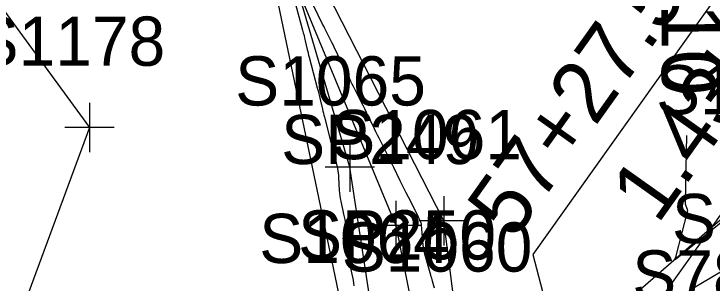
# Model space of a CAD drawing. Extents: x 816928 to 825690, y 436959 to 448212.
# Drawn here: x 818922.8 to 818979.4, y 445230.1 to 445252 of the extents above; entities that cross this region are included whole.
import ezdxf

# ---------------------------------------------------------------- set-up
doc = ezdxf.new("R2010")
doc.units = 0
for name, color, linetype in [('SURVEY - CONTOURS - Index with Text', 7, 'Continuous'), ('SURVEY - CONTOURS - Intermediate with optional Text', 7, 'Continuous'), ('SURVEY - DRAINAGE - Bridges Text', 7, 'Continuous'), ('SURVEY - DTM - Breaklines', 7, 'Continuous'), ('SURVEY - DTM - Breaklines - Points - Locators', 7, 'Continuous'), ('SURVEY - DTM - Breaklines - Points - Numbers', 7, 'Continuous'), ('SURVEY - PROPERTY - Parcels', 7, 'Continuous'), ('SURVEY - PROPERTY - ROW Lines', 7, 'Continuous'), ('SURVEY - UTILITIES - Telephone (Underground) - Points - Numbers', 7, 'Continuous'), ('SURVEY - VEGETATION - Features - Points - Locators', 7, 'Continuous'), ('SURVEY - VEGETATION - Features - Points - Numbers', 7, 'Continuous'), ('SURVEY - VEGETATION - Features with Text', 7, 'Continuous')]:
    doc.layers.add(name, color=color, linetype=linetype)

msp = doc.modelspace()

# ---------------------------------------------------------------- linework, layer by layer
at = {"layer": 'SURVEY - CONTOURS - Index with Text'}
msp.add_lwpolyline([(818977.365, 445242.093), (818977.255, 445236.694), (818977.257, 445236.612), (818977.268, 445236.531), (818977.287, 445236.452), (818977.314, 445236.374), (818977.416, 445236.122), (818977.433, 445236.067), (818977.441, 445236.012), (818977.44, 445235.957), (818977.43, 445235.901), (818976.493, 445232.325), (818976.491, 445232.318), (818976.491, 445232.312), (818976.492, 445232.305), (818976.494, 445232.299), (818976.503, 445232.277), (818976.505, 445232.273), (818976.505, 445232.268), (818976.505, 445232.264), (818976.504, 445232.259), (818976.433, 445232.064), (818976.424, 445232.031), (818976.427, 445232.016), (818976.443, 445232.018), (818976.471, 445232.037), (818976.698, 445232.223), (818976.7, 445232.225), (818976.702, 445232.226), (818976.704, 445232.227), (818976.706, 445232.229), (818976.712, 445232.232), (818976.713, 445232.233), (818976.715, 445232.234), (818976.716, 445232.235), (818976.717, 445232.236), (818980.448, 445235.262)], dxfattribs=at)
at = {"layer": 'SURVEY - CONTOURS - Intermediate with optional Text'}
for points in [[(818945.447, 445253.599), (818946.234, 445250.644), (818946.29, 445250.429), (818946.345, 445250.213), (818946.398, 445249.996), (818946.448, 445249.779), (818946.611, 445249.07), (818946.646, 445248.918), (818946.683, 445248.767), (818946.721, 445248.615), (818946.76, 445248.464), (818947.423, 445245.954), (818947.484, 445245.719), (818947.543, 445245.483), (818947.601, 445245.247), (818947.656, 445245.01), (818947.835, 445244.236), (818947.874, 445244.07), (818947.914, 445243.905), (818947.955, 445243.74), (818947.998, 445243.575), (818948.611, 445241.234), (818948.676, 445240.983), (818948.739, 445240.731), (818948.801, 445240.478), (818948.86, 445240.226), (818949.052, 445239.399), (818949.089, 445239.221), (818949.118, 445239.042), (818949.139, 445238.862), (818949.152, 445238.681), (818949.202, 445237.637), (818949.217, 445237.414), (818949.243, 445237.192), (818949.278, 445236.971), (818949.323, 445236.752), (818949.559, 445235.715), (818949.606, 445235.492), (818949.644, 445235.268), (818949.673, 445235.042), (818949.694, 445234.815), (818949.823, 445233.081), (818949.855, 445232.734), (818949.899, 445232.389), (818949.957, 445232.046), (818950.026, 445231.705), (818950.274, 445230.593), (818950.324, 445230.354), (818950.365, 445230.114), (818950.399, 445229.873)], [(818956.932, 445229.705), (818956.771, 445230.266), (818956.736, 445230.386), (818956.702, 445230.506), (818956.667, 445230.626), (818956.633, 445230.746), (818956.197, 445232.263), (818956.117, 445232.57), (818956.054, 445232.879), (818956.007, 445233.191), (818955.975, 445233.506), (818955.876, 445234.845), (818955.868, 445234.913), (818955.854, 445234.979), (818955.833, 445235.044), (818955.805, 445235.107), (818955.706, 445235.31), (818955.684, 445235.353), (818955.663, 445235.397), (818955.641, 445235.44), (818955.619, 445235.483), (818954.809, 445237.095), (818954.644, 445237.424), (818954.48, 445237.753), (818954.317, 445238.083), (818954.155, 445238.413), (818953.626, 445239.491), (818953.513, 445239.722), (818953.399, 445239.953), (818953.284, 445240.183), (818953.169, 445240.413), (818952.566, 445241.611), (818952.437, 445241.868), (818952.309, 445242.125), (818952.182, 445242.383), (818952.056, 445242.641), (818951.409, 445243.964), (818951.27, 445244.248), (818951.13, 445244.531), (818950.99, 445244.813), (818950.848, 445245.096), (818950.363, 445246.06), (818950.259, 445246.267), (818950.156, 445246.475), (818950.054, 445246.682), (818949.952, 445246.89), (818949.1, 445248.641), (818948.978, 445248.89), (818948.855, 445249.139), (818948.732, 445249.387), (818948.608, 445249.635), (818948.2, 445250.444), (818948.113, 445250.618), (818948.027, 445250.792), (818947.941, 445250.966), (818947.857, 445251.14), (818946.757, 445253.409)], [(818980.118, 445230.994), (818977.936, 445229.697)]]:
    msp.add_lwpolyline(points, dxfattribs=at)
at = {"layer": 'SURVEY - DRAINAGE - Bridges Text'}
msp.add_line((818986.837, 445263.289), (818964.904, 445232.428), dxfattribs=at)
msp.add_lwpolyline([(818964.904, 445232.428), (818977.092, 445185.746)], dxfattribs=at)
at = {"layer": 'SURVEY - DTM - Breaklines'}
for points in [[(819073.298, 445355.122), (819048.115, 445322.006), (819023.42, 445284.723), (818992.563, 445243.615), (818984.238, 445238.804), (818960.537, 445218.165), (818958.862, 445226.04), (818957.684, 445235.166), (818941.199, 445267.453), (818950.993, 445220.447), (818950.259, 445210.542), (818939.42, 445207.694)], [(818955.127, 445214.291), (818952.003, 445226.736), (818950.052, 445239.527), (818945.78, 445254.112), (818953.794, 445234.774), (818955.325, 445227.021), (818958.675, 445215.535)]]:
    msp.add_lwpolyline(points, dxfattribs=at)
at = {"layer": 'SURVEY - DTM - Breaklines - Points - Locators'}
for p, q in [((818950.052, 445241.527), (818950.052, 445237.527)), ((818952.052, 445239.527), (818948.052, 445239.527)), ((818957.684, 445237.166), (818957.684, 445233.166)), ((818953.794, 445236.774), (818953.794, 445232.774)), ((818959.684, 445235.166), (818955.684, 445235.166)), ((818955.794, 445234.774), (818951.794, 445234.774))]:
    msp.add_line(p, q, dxfattribs=at)
at = {"layer": 'SURVEY - PROPERTY - Parcels'}
msp.add_line((818939.168, 445178.006), (819170.276, 445503.188), dxfattribs=at)
at = {"layer": 'SURVEY - PROPERTY - ROW Lines'}
msp.add_line((818939.168, 445178.006), (819182.874, 445520.914), dxfattribs=at)
at = {"layer": 'SURVEY - VEGETATION - Features - Points - Locators'}
for p, q in [((818928.958, 445244.751), (818928.958, 445240.751)), ((818930.958, 445242.751), (818926.958, 445242.751))]:
    msp.add_line(p, q, dxfattribs=at)
at = {"layer": 'SURVEY - VEGETATION - Features with Text'}
msp.add_lwpolyline([(818921.649, 445531.075), (818911.357, 445419.447), (818895.02, 445347.602), (818900.539, 445320.739), (818919.801, 445285.725), (818871.556, 445256.506), (818910.143, 445268.505), (818928.958, 445242.751), (818875.35, 445097.529)], dxfattribs=at)

# ---------------------------------------------------------------- texts
at = {"layer": 'SURVEY - CONTOURS - Index with Text'}
msp.add_text('310', height=5, rotation=270.52, dxfattribs=at).set_placement((818975.292, 445256.499))
at = {"layer": 'SURVEY - DRAINAGE - Bridges Text'}
for s, p in [('57+27.53', (818963.376, 445233.515)), ("1.43'", (818975.022, 445234.798))]:
    msp.add_text(s, height=5, rotation=54.5985, dxfattribs=at).set_placement(p)
at = {"layer": 'SURVEY - DTM - Breaklines - Points - Numbers'}
for s, p in [('S1065', (818940.764, 445244.527)), ('S1058', (818974.903, 445243.804)), ('S1061', (818948.554, 445240.166)), ('SP249', (818944.49, 445239.774)), ('S1029', (818976.188, 445233.351)), ('S1064', (818942.715, 445231.736)), ('SP250', (818945.864, 445232.021)), ('S1060', (818949.401, 445231.04))]:
    msp.add_text(s, height=4, dxfattribs=at).set_placement(p)
at = {"layer": 'SURVEY - UTILITIES - Telephone (Underground) - Points - Numbers'}
msp.add_text('S787', height=4, dxfattribs=at).set_placement((818972.967, 445228.767))
at = {"layer": 'SURVEY - VEGETATION - Features - Points - Numbers'}
msp.add_text('S1178', height=4, dxfattribs=at).set_placement((818919.623, 445247.751))

doc.saveas('drawing.dxf')
